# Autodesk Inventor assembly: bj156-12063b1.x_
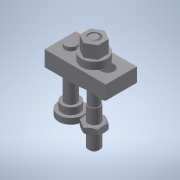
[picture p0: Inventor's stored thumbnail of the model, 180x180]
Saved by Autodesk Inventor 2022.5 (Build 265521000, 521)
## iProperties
Part Number: bj156-12063b1.x_
Material: 一般
Document SubType Name: Assembly
Designer: ImaoCorp
Sending System: SOLIDWORKS 2017-2017317
MC: AMD64
MC_MODEL: Intel64 Family 6 Model 60 Stepping 3, GenuineIntel
OS: Windows_NT
FRU: Parasolid Version 29.0, build 201,  4-17-2017
FORMAT: text
GUISE: transmit
KEY: bj156-12063b1
FILE: bj156-12063b1.x_t
DATE: Fri Mar 15 10:20:47 2019
Author: ImaoCorp
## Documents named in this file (6)
- X:\14_SW2022-Inv2022\00_全2023-1023新製品(TCC)まで\b\bj156-12063b1\BJ156-12063B1.iam
- X:\14_SW2022-Inv2022\00_全2023-1023新製品(TCC)まで\b\bj156-12063b1\bj156-12063b1_01.ipt
- X:\14_SW2022-Inv2022\00_全2023-1023新製品(TCC)まで\b\bj156-12063b1\bj156-12063b1_02.ipt
- X:\14_SW2022-Inv2022\00_全2023-1023新製品(TCC)まで\b\bj156-12063b1\bj156-12063b1_03.ipt
- X:\14_SW2022-Inv2022\00_全2023-1023新製品(TCC)まで\b\bj156-12063b1\bj156-12063b1_04.ipt
- X:\14_SW2022-Inv2022\00_全2023-1023新製品(TCC)まで\b\bj156-12063b1\bj156-12063b1_05.ipt
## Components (5 placed, 5 different names)
1. bj156-12063b1_01
2. bj156-12063b1_02
3. bj156-12063b1_03
4. bj156-12063b1_04
5. bj156-12063b1_05
